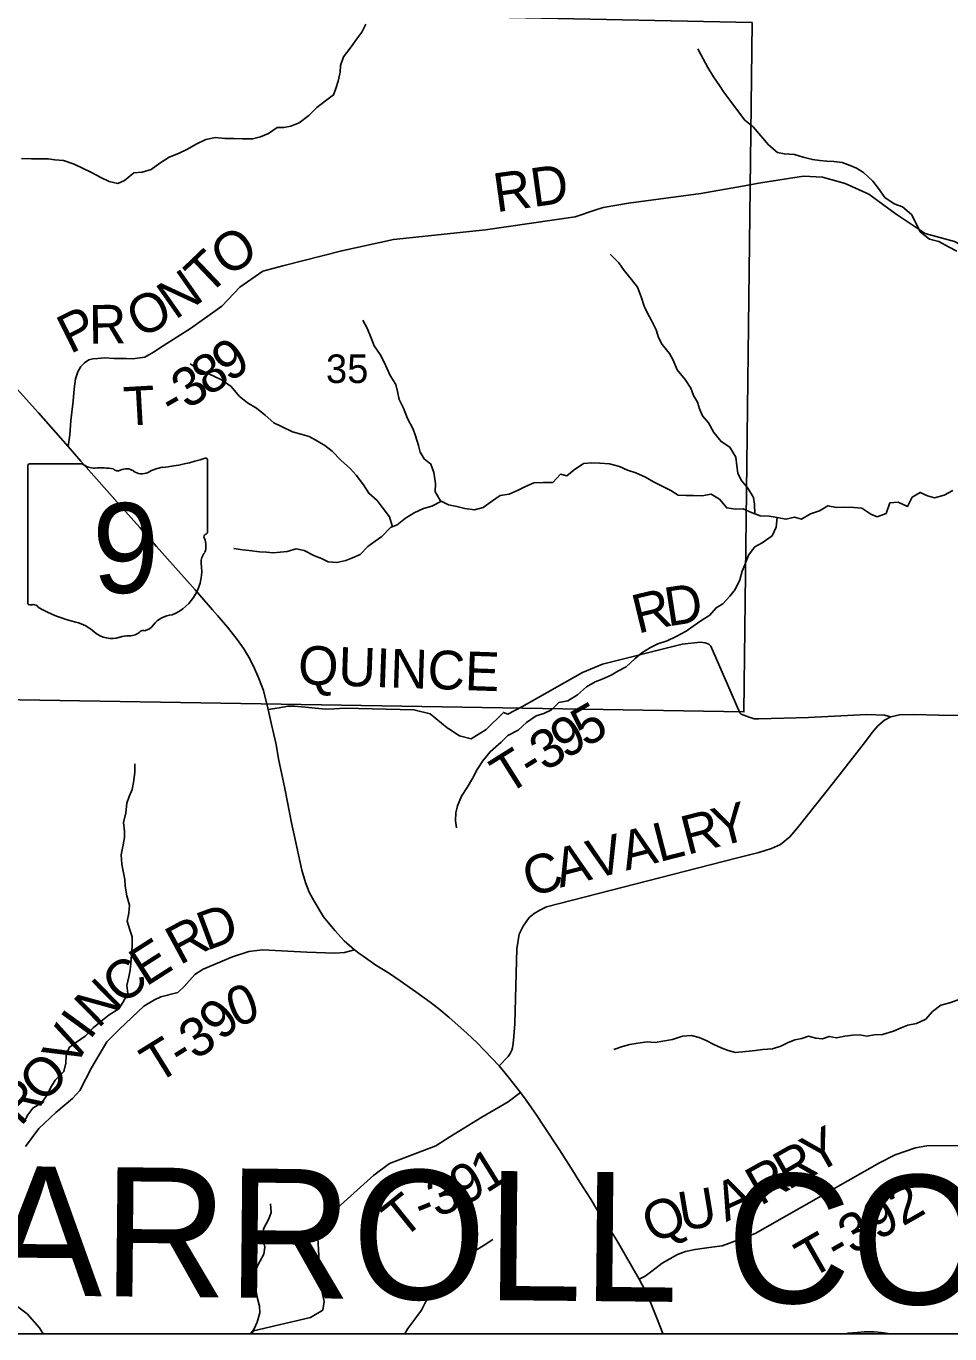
# Model space of a CAD drawing. Extents: x -3.6 to 34, y 0 to 32.8.
# Drawn here: x 0.333 to 1.688, y 26.043 to 27.961 of the extents above; entities that cross this region are included whole.
import ezdxf

# ---------------------------------------------------------------- set-up
doc = ezdxf.new("R2010")
doc.units = 0
for name, color, linetype in [('GM_X_Corporation', 7, 'Continuous'), ('GM_X_County_Road', 7, 'Continuous'), ('GM_X_County_Road_Text', 7, 'Continuous'), ('GM_X_County_Text', 7, 'Continuous'), ('GM_X_Minor_River', 7, 'Continuous'), ('GM_X_Section_Text', 7, 'Continuous'), ('GM_X_State_Location', 7, 'Continuous'), ('GM_X_State_Route', 7, 'Continuous'), ('GM_X_State_Shield', 7, 'Continuous'), ('GM_X_Township_Road', 7, 'Continuous'), ('GM_X_Township_Road_Text', 7, 'Continuous'), ('SH_Data', 7, 'Continuous')]:
    doc.layers.add(name, color=color, linetype=linetype)

msp = doc.modelspace()

# ---------------------------------------------------------------- linework, layer by layer
at = {"layer": 'GM_X_Corporation'}
for points in [[(3.1705, 28.9337), (3.1705, 32.8429), (-3.6295, 32.8429), (-3.6295, 26.0429), (2.3706, 26.0429), (2.3712, 26.0804), (2.3716, 26.1248), (2.3732, 26.2253), (2.3789, 26.6097), (2.3911, 27.5117), (2.3952, 27.9336), (2.3997, 28.282), (2.4082, 28.9473), (2.5416, 28.945), (2.5837, 28.9442), (2.8343, 28.9397)], [(1.398, 27.966), (1.386, 26.9549), (0.2053, 26.9746), (0.2336, 27.9902)]]:
    msp.add_lwpolyline(points, close=True, dxfattribs=at)
msp.add_lwpolyline([(-2.8635, 26.0429), (2.3706, 26.0429), (2.3712, 26.0804), (2.3716, 26.1248), (2.3732, 26.2253), (2.3789, 26.6097), (2.3911, 27.5117), (2.3952, 27.9336), (2.3997, 28.282), (2.4082, 28.9473), (2.5416, 28.945), (2.5837, 28.9442), (2.8343, 28.9397), (3.1705, 28.9337), (3.1705, 30.458), (3.0419, 30.4594), (1.7819, 30.4857), (1.2437, 30.4948), (0.4055, 30.5105), (0.3556, 30.5115), (0.2578, 30.5133), (0.2583, 30.5905), (-0.398, 30.5946), (-0.453, 30.5952)], dxfattribs=at)
at = {"layer": 'GM_X_County_Road'}
msp.add_lwpolyline([(1.7122, 26.9497), (1.6716, 26.9501), (1.635, 26.9512), (1.6143, 26.9507), (1.6014, 26.9478), (1.5921, 26.943), (1.5821, 26.9344), (1.5738, 26.925), (1.5643, 26.9118), (1.5175, 26.8517), (1.4643, 26.7848), (1.4532, 26.7717), (1.4394, 26.7606), (1.4261, 26.7546), (1.4077, 26.7486), (1.3746, 26.7403), (1.0964, 26.6689), (1.0864, 26.6642), (1.0783, 26.6593), (1.0708, 26.6533), (1.0621, 26.641), (1.0565, 26.629), (1.0527, 26.6073), (1.0513, 26.5535), (1.0498, 26.4974), (1.0481, 26.473), (1.0472, 26.4659), (1.0465, 26.4622), (1.0453, 26.4589), (1.0431, 26.454), (1.0402, 26.4498), (1.0268, 26.4357)], dxfattribs=at)
at = {"layer": 'GM_X_Minor_River'}
for points in [[(0.8314, 27.9639), (0.8255, 27.952), (0.8181, 27.9421), (0.81, 27.9306), (0.7985, 27.916), (0.7941, 27.903), (0.7939, 27.8931), (0.7907, 27.8802), (0.7874, 27.8695), (0.7842, 27.86), (0.7722, 27.8514), (0.7595, 27.8417), (0.7479, 27.8298), (0.7337, 27.819), (0.7213, 27.8142), (0.7111, 27.8122), (0.7013, 27.812), (0.6885, 27.8031), (0.6769, 27.7984), (0.6652, 27.7955), (0.6504, 27.7953), (0.6379, 27.7959), (0.6247, 27.7961), (0.6111, 27.7974), (0.5967, 27.7945), (0.5828, 27.7878), (0.5697, 27.7804), (0.5565, 27.7738), (0.543, 27.7686), (0.5291, 27.7597), (0.5168, 27.7504), (0.5036, 27.7468), (0.4911, 27.7455), (0.4777, 27.7343), (0.4679, 27.7299), (0.455, 27.7328), (0.4428, 27.7387), (0.4279, 27.7468), (0.4169, 27.7519), (0.4035, 27.7586), (0.3879, 27.7636), (0.3754, 27.7646), (0.3656, 27.766), (0.3512, 27.7661), (0.341, 27.7663), (0.3266, 27.7665)], [(1.698, 27.6308), (1.6858, 27.6371), (1.6716, 27.6448), (1.658, 27.6484), (1.6446, 27.6592), (1.6387, 27.6713), (1.6317, 27.6845), (1.6187, 27.6956), (1.6061, 27.7), (1.5927, 27.7093), (1.5835, 27.7228), (1.575, 27.7333), (1.5612, 27.746), (1.5512, 27.7527), (1.5417, 27.7564), (1.5299, 27.7607), (1.5178, 27.7625), (1.5076, 27.7627), (1.4973, 27.7637), (1.4863, 27.765), (1.473, 27.7686), (1.4601, 27.7726), (1.4453, 27.7735), (1.4351, 27.7753), (1.4217, 27.7868), (1.3994, 27.8131), (1.3871, 27.8231), (1.3736, 27.8408), (1.3666, 27.8505), (1.3566, 27.864), (1.35, 27.8738), (1.3411, 27.8866), (1.333, 27.9001), (1.3263, 27.9129), (1.3182, 27.9276)], [(1.4017, 27.2456), (1.4015, 27.2596), (1.3999, 27.2695), (1.3917, 27.283), (1.3817, 27.295), (1.377, 27.3052), (1.3757, 27.3158), (1.374, 27.3287), (1.3651, 27.3434), (1.3525, 27.3515), (1.3417, 27.3646), (1.3339, 27.379), (1.3251, 27.3891), (1.3208, 27.3993), (1.3176, 27.4091), (1.3121, 27.4193), (1.3078, 27.4298), (1.2997, 27.4426), (1.2881, 27.4565), (1.2819, 27.4708), (1.2768, 27.4806), (1.266, 27.4937), (1.2605, 27.5043), (1.2574, 27.5152), (1.2503, 27.5292), (1.2445, 27.5397), (1.2394, 27.5499), (1.2354, 27.5639), (1.2296, 27.5778), (1.2211, 27.5891), (1.2103, 27.6022), (1.2025, 27.6139), (1.1895, 27.6266)], [(0.8756, 27.4351), (0.8671, 27.4482), (0.8628, 27.458), (0.8585, 27.4682), (0.8523, 27.4791), (0.8438, 27.4919), (0.8387, 27.5044), (0.8332, 27.518), (0.8269, 27.5296)], [(0.8704, 27.2266), (0.866, 27.2413), (0.8556, 27.2552), (0.8479, 27.2649), (0.8356, 27.2758), (0.8282, 27.2882), (0.8174, 27.3021), (0.8082, 27.3118), (0.7948, 27.3241), (0.7821, 27.3372), (0.7714, 27.3458), (0.758, 27.3536), (0.7481, 27.3591), (0.7379, 27.362), (0.7238, 27.3656), (0.7078, 27.3737), (0.6967, 27.3792), (0.6837, 27.39), (0.6711, 27.4005), (0.6581, 27.4083), (0.6458, 27.4183), (0.6339, 27.4322), (0.6209, 27.4415), (0.6083, 27.4474), (0.5988, 27.4518), (0.5862, 27.4577), (0.5736, 27.4654)], [(1.6922, 27.2796), (1.6794, 27.2729), (1.6655, 27.2689), (1.6552, 27.2718), (1.6446, 27.2769), (1.6326, 27.2699), (1.6259, 27.2565), (1.6122, 27.2624), (1.5998, 27.2615), (1.5943, 27.2462), (1.5815, 27.2411), (1.572, 27.2451), (1.559, 27.2536), (1.5473, 27.255), (1.5336, 27.2552), (1.5215, 27.255), (1.509, 27.2574), (1.4966, 27.2497), (1.4835, 27.2457), (1.4703, 27.2379), (1.4601, 27.2408), (1.4476, 27.2375), (1.4347, 27.24), (1.423, 27.2421), (1.4097, 27.2427), (1.3979, 27.247), (1.385, 27.2529), (1.3736, 27.2524), (1.3607, 27.2541), (1.3503, 27.2668), (1.3377, 27.2746), (1.3241, 27.2721), (1.312, 27.2723), (1.3014, 27.2725), (1.2897, 27.2731), (1.2786, 27.2798), (1.2649, 27.2864), (1.2535, 27.2927), (1.2416, 27.2994), (1.2275, 27.3056), (1.2154, 27.3096), (1.2032, 27.3151), (1.1888, 27.3191), (1.1744, 27.32), (1.163, 27.3202), (1.1505, 27.3193), (1.137, 27.3103), (1.1262, 27.3014), (1.1167, 27.3036), (1.1055, 27.2916), (1.0915, 27.2914), (1.0779, 27.2912), (1.0648, 27.2849), (1.055, 27.2802), (1.0418, 27.2743), (1.0286, 27.2726), (1.0159, 27.2637), (1.0035, 27.2548), (0.9907, 27.2515), (0.9767, 27.2532), (0.9649, 27.2561), (0.9528, 27.2586), (0.941, 27.2648), (0.9332, 27.278), (0.9334, 27.2902), (0.9313, 27.3061), (0.9269, 27.3185), (0.917, 27.326), (0.9112, 27.3358), (0.9084, 27.3456), (0.9044, 27.36), (0.9008, 27.3698), (0.8926, 27.3852), (0.8867, 27.4003), (0.8805, 27.4131), (0.8777, 27.4249), (0.8756, 27.4351)], [(0.9424, 27.2641), (0.9282, 27.257), (0.9158, 27.2534), (0.9022, 27.2472), (0.8895, 27.2394), (0.8772, 27.2293), (0.8674, 27.2254), (0.8551, 27.2123), (0.8453, 27.2053), (0.8345, 27.1975), (0.8233, 27.186), (0.812, 27.1812), (0.8019, 27.1773), (0.789, 27.1741), (0.7762, 27.175), (0.7663, 27.1798), (0.756, 27.1838), (0.7411, 27.1916), (0.729, 27.1944), (0.7162, 27.1904), (0.7056, 27.1891), (0.6954, 27.1882), (0.6855, 27.1892), (0.6753, 27.1898), (0.6601, 27.1919), (0.6507, 27.1929), (0.6378, 27.1949)], [(1.4348, 27.24), (1.433, 27.2259), (1.4272, 27.2133), (1.4126, 27.2032), (1.4021, 27.197), (1.3928, 27.1851), (1.3873, 27.1709), (1.3833, 27.1614), (1.3801, 27.1488), (1.3731, 27.1347), (1.3653, 27.125), (1.3552, 27.1135), (1.3451, 27.1077), (1.3358, 27.0969), (1.3242, 27.0895), (1.3114, 27.0809), (1.3013, 27.0736), (1.2867, 27.0658), (1.2735, 27.0591), (1.2596, 27.0551), (1.2487, 27.0496), (1.236, 27.0418), (1.2263, 27.0333), (1.2132, 27.021), (1.2012, 27.0147), (1.1914, 27.0089), (1.1779, 27.003), (1.1677, 26.999), (1.155, 26.9916), (1.1419, 26.98), (1.1276, 26.9715), (1.1144, 26.9686), (1.1036, 26.9582), (1.0923, 26.9527), (1.0814, 26.9495), (1.0672, 26.9394), (1.0549, 26.9282), (1.0395, 26.9204), (1.0298, 26.9104), (1.0137, 26.8965), (1.0029, 26.8834), (0.9948, 26.8707), (0.9878, 26.8573), (0.98, 26.8443), (0.9715, 26.8316), (0.9657, 26.8171), (0.9632, 26.8068), (0.963, 26.7954), (0.9643, 26.7848)], [(0.3292, 26.3521), (0.3358, 26.3639), (0.3429, 26.3739), (0.3564, 26.3821), (0.3645, 26.394), (0.3689, 26.4039), (0.3756, 26.4151), (0.3886, 26.4274), (0.3915, 26.44), (0.3921, 26.4506), (0.3964, 26.4628), (0.4069, 26.4706), (0.42, 26.4795), (0.4316, 26.4915), (0.4454, 26.5031), (0.4551, 26.5105), (0.469, 26.5194), (0.4749, 26.529), (0.4823, 26.542), (0.481, 26.5538), (0.4838, 26.5667), (0.4856, 26.5762), (0.487, 26.5861), (0.4879, 26.5987), (0.4885, 26.6116), (0.4887, 26.6249), (0.4851, 26.6355), (0.4815, 26.648), (0.4836, 26.6598), (0.485, 26.6716), (0.481, 26.6852), (0.4785, 26.6996), (0.478, 26.7094), (0.4755, 26.7215), (0.4735, 26.7318), (0.4725, 26.7454), (0.4753, 26.7603), (0.4775, 26.7706), (0.4777, 26.7801), (0.476, 26.7926), (0.4792, 26.8071), (0.4809, 26.8211), (0.4842, 26.8311), (0.4889, 26.8414), (0.4907, 26.8517), (0.4927, 26.8661), (0.4925, 26.879)], [(1.7002, 26.5325), (1.6878, 26.5281), (1.6746, 26.5249), (1.6626, 26.5156), (1.6529, 26.5044), (1.639, 26.4981), (1.6262, 26.4956), (1.6164, 26.4917), (1.6055, 26.487), (1.5893, 26.4818), (1.5776, 26.4812), (1.5662, 26.4795), (1.5556, 26.4813), (1.5458, 26.4808), (1.5337, 26.4794), (1.5216, 26.477), (1.511, 26.4791), (1.5012, 26.4755), (1.4914, 26.4765), (1.4807, 26.4794), (1.4709, 26.4762), (1.4607, 26.4741), (1.4498, 26.4698), (1.4401, 26.4647), (1.4276, 26.4611), (1.4133, 26.4598), (1.4027, 26.4585), (1.3887, 26.4571), (1.3736, 26.4557), (1.3626, 26.4586), (1.3523, 26.4622), (1.3416, 26.4674), (1.3306, 26.4733), (1.3203, 26.4773), (1.3089, 26.4802), (1.2957, 26.4796), (1.281, 26.4748), (1.267, 26.4723), (1.2557, 26.4703), (1.244, 26.4712), (1.2304, 26.4691), (1.2187, 26.467), (1.2077, 26.4642), (1.1949, 26.4598)], [(0.6625, 26.0429), (0.6674, 26.0501), (0.6722, 26.06), (0.6761, 26.0738), (0.6756, 26.0836), (0.6724, 26.0946), (0.6704, 26.1048), (0.6683, 26.1158), (0.6678, 26.1253), (0.6695, 26.1352), (0.6736, 26.1447), (0.682, 26.1596), (0.6834, 26.1699), (0.6798, 26.1843), (0.6811, 26.1968), (0.6892, 26.2114), (0.6925, 26.2209), (0.6916, 26.2334)], [(0.8885, 26.0429), (0.8929, 26.0509), (0.9033, 26.0643), (0.913, 26.0778), (0.9192, 26.0904), (0.9281, 26.1046), (0.9382, 26.1131), (0.9528, 26.122), (0.964, 26.134), (0.9718, 26.1455), (0.9806, 26.1578), (0.9908, 26.164), (1.005, 26.1729), (1.0178, 26.1811)], [(1.6028, 26.0429), (1.6011, 26.0431), (1.5871, 26.0448), (1.5768, 26.0458), (1.5624, 26.0459), (1.5522, 26.045), (1.5386, 26.0437), (1.5355, 26.0429)]]:
    msp.add_lwpolyline(points, dxfattribs=at)
at = {"layer": 'GM_X_State_Route'}
msp.add_lwpolyline([(1.267, 26.0429), (1.2668, 26.0435), (1.2593, 26.0635), (1.2495, 26.088), (1.2411, 26.1063), (1.2325, 26.1232), (1.2119, 26.1587), (1.1988, 26.1805), (1.1842, 26.204), (1.1714, 26.2238), (1.1602, 26.242), (1.1451, 26.2654), (1.1325, 26.2859), (1.1153, 26.3127), (1.0913, 26.3488), (1.082, 26.3631), (1.0667, 26.3854), (1.058, 26.3969), (1.04, 26.4197), (1.0268, 26.4357), (0.9945, 26.4695), (0.9794, 26.484), (0.9538, 26.5069), (0.9386, 26.5194), (0.9256, 26.5293), (0.9047, 26.5447), (0.8819, 26.5606), (0.866, 26.5712), (0.8461, 26.5838), (0.8273, 26.5966), (0.8209, 26.6013), (0.815, 26.6062), (0.7998, 26.6192), (0.7857, 26.6344), (0.7695, 26.6545), (0.7554, 26.6775), (0.7481, 26.6908), (0.743, 26.7047), (0.7374, 26.7228), (0.7262, 26.7745), (0.7227, 26.7899), (0.7128, 26.8425), (0.7032, 26.8864), (0.6997, 26.9072), (0.6933, 26.9365), (0.6882, 26.9586), (0.6811, 26.9866), (0.6745, 27.0039), (0.6666, 27.0223), (0.6598, 27.0351), (0.6523, 27.0474), (0.6428, 27.0611), (0.6286, 27.0791), (0.6141, 27.0965), (0.6065, 27.1048), (0.5812, 27.1343), (0.5244, 27.1978), (0.5002, 27.2256), (0.4747, 27.2537), (0.4134, 27.3228), (0.3947, 27.3442), (0.3515, 27.3935), (0.298, 27.453)], dxfattribs=at)
at = {"layer": 'GM_X_State_Shield'}
for p, q in [((0.3355, 27.3156), (0.3355, 27.1154)), ((0.4153, 27.319), (0.3381, 27.319)), ((0.5991, 27.2193), (0.5991, 27.324)), ((0.5991, 27.2193), (0.5991, 27.2193))]:
    msp.add_line(p, q, dxfattribs=at)
for centre, radius, start, end in [((0.3385, 27.316), 0.00305, 98.1301, 188.1301), ((0.4337, 27.3422), 0.0296, 231.6195, 271.1119), ((0.4435, 27.2066), 0.1064, 80.4867, 94.9883), ((0.4677, 27.317), 0.00855, 219.7921, 297.1024), ((0.4802, 27.2939), 0.0178, 54.4667, 119.1411), ((0.5409, 27.2579), 0.0563, 97.3462, 120.7689), ((0.5052, 27.5918), 0.2796, 275.8445, 288.9065), ((0.5962, 27.3244), 0.00294, 351.8621, 97.738), ((0.5031, 27.3256), 0.0214, 233.8562, 294.8282), ((0.5985, 27.2116), 0.00454, 107.944, 210.337), ((0.596, 27.2189), 0.00314, 289.6038, 7.7341), ((0.5696, 27.1984), 0.0273, 340.033, 23.6496), ((0.6097, 27.1755), 0.0198, 136.8065, 186.9296), ((0.5209, 27.1621), 0.0699, 292.3089, 8.9858), ((0.3385, 27.115), 0.00308, 171.9584, 258.3066), ((0.339, 27.1355), 0.0235, 267.339, 280.6039), ((0.3438, 27.1039), 0.00848, 29.7484, 93.2717), ((0.4509, 27.2837), 0.2019, 240.4129, 257.1985), ((0.3907, 27.0255), 0.0632, 47.1842, 75.836), ((0.5018, 27.096), 0.0226, 282.8732, 323.2771), ((0.5504, 27.0593), 0.0383, 94.4031, 142.5768), ((0.459, 27.1029), 0.0401, 230.7004, 286.2918), ((0.4822, 27.0337), 0.0329, 85.6951, 111.2099), ((0.4851, 27.0879), 0.0214, 268.777, 315.5493), ((0.5044, 27.0685), 0.00601, 65.7517, 132.6484)]:
    msp.add_arc(centre, radius, start, end, dxfattribs=at)
at = {"layer": 'GM_X_Township_Road'}
for points in [[(1.4048, 27.7298), (1.4136, 27.7314), (1.4735, 27.7407), (1.5009, 27.7394), (1.5346, 27.7299), (1.5692, 27.7143), (1.609, 27.6852), (1.6519, 27.6569), (1.6946, 27.6449), (1.7179, 27.6327), (1.746, 27.6205), (1.7894, 27.6086), (1.8209, 27.6012), (1.8495, 27.5978), (1.8671, 27.6001)], [(1.1793, 27.6949), (1.2165, 27.7011), (1.3227, 27.7153), (1.3921, 27.7276), (1.4048, 27.7298)], [(0.3947, 27.3442), (0.3974, 27.3615), (0.399, 27.3822), (0.4023, 27.4106), (0.4038, 27.4288), (0.4058, 27.4434), (0.4088, 27.4539), (0.4134, 27.4617), (0.4186, 27.467), (0.4252, 27.4712), (0.4311, 27.4728), (0.4384, 27.4735), (0.4482, 27.4743), (0.4622, 27.4734), (0.4802, 27.4732), (0.4896, 27.473), (0.5071, 27.4751), (0.5199, 27.4826), (0.5342, 27.4919), (0.5741, 27.5172), (0.6203, 27.5501), (0.6468, 27.5779), (0.6805, 27.6012), (0.7096, 27.6094), (0.7962, 27.6315), (0.8719, 27.6481), (1.007, 27.6621), (1.1386, 27.6811), (1.1673, 27.6908), (1.1793, 27.6949)], [(0.9679, 26.9206), (0.9687, 26.9201), (0.9859, 26.9155), (1.008, 26.9294), (1.0333, 26.9543), (1.0399, 26.9518), (1.0602, 26.9625), (1.1492, 27.0128), (1.1786, 27.0249), (1.2951, 27.0542), (1.3224, 27.0575), (1.329, 27.0564), (1.3343, 27.0542), (1.3374, 27.0513), (1.3623, 26.9941), (1.3799, 26.9537), (1.3818, 26.9517), (1.3937, 26.9473), (1.4011, 26.9451), (1.4079, 26.9449), (1.4805, 26.9469), (1.5664, 26.9514), (1.5923, 26.9503), (1.6014, 26.9478)], [(0.6882, 26.9586), (0.7044, 26.9611), (0.717, 26.9633), (0.7271, 26.9636), (0.7724, 26.959), (0.785, 26.9596)], [(0.785, 26.9596), (0.8004, 26.9605), (0.902, 26.9582), (0.9257, 26.9522), (0.9505, 26.9319), (0.9555, 26.9287), (0.9679, 26.9206)], [(0.815, 26.6062), (0.8, 26.6022), (0.7861, 26.6012), (0.7449, 26.6026), (0.6801, 26.6062), (0.6598, 26.6035), (0.636, 26.5958), (0.5927, 26.5778), (0.5807, 26.5701), (0.5649, 26.5522), (0.5556, 26.5437), (0.5307, 26.5369), (0.5217, 26.5327), (0.506, 26.5234), (0.4699, 26.4898), (0.4514, 26.4709), (0.4289, 26.433), (0.412, 26.3996), (0.4011, 26.3882), (0.3769, 26.3673), (0.352, 26.344), (0.3321, 26.3177)], [(1.058, 26.3969), (1.04, 26.3832), (1.0017, 26.3607), (0.9547, 26.3319), (0.9343, 26.3185), (0.8661, 26.2925), (0.8433, 26.2757), (0.7601, 26.2007), (0.7632, 26.149), (0.766, 26.1099), (0.7702, 26.0902), (0.7682, 26.0776), (0.7502, 26.0666), (0.6666, 26.0472), (0.6639, 26.0429)], [(1.2325, 26.1232), (1.241, 26.1275), (1.2507, 26.1349), (1.2661, 26.1463), (1.2885, 26.1593), (1.3003, 26.1635), (1.3142, 26.1666), (1.3351, 26.1697), (1.3539, 26.1718), (1.3688, 26.1775), (1.4026, 26.19), (1.5847, 26.2936), (1.6076, 26.3056), (1.6374, 26.3158), (1.6541, 26.3184), (1.861, 26.3204)], [(0.3584, 26.0429), (0.353, 26.0518), (0.3347, 26.072), (0.3173, 26.0853)]]:
    msp.add_lwpolyline(points, dxfattribs=at)
at = {"layer": 'SH_Data'}
msp.add_line((-3.6295, 26.0429), (3.1705, 26.0429), dxfattribs=at)

# ---------------------------------------------------------------- texts
at = {"layer": 'GM_X_County_Road_Text'}
for s, rotation, p in [('Y', 14.5707, (1.348, 26.7567)), ('R', 14.4329, (1.3026, 26.7451)), ('V', 14.4338, (1.1646, 26.7095)), ('A', 14.4321, (1.213, 26.722)), ('L', 14.4323, (1.2615, 26.7345)), ('A', 14.5557, (1.1162, 26.697)), ('C', 18.696, (1.0731, 26.6823))]:
    msp.add_text(s, height=0.0568, rotation=rotation, dxfattribs=at).set_placement(p)
at = {"layer": 'GM_X_County_Text'}
msp.add_text('CARROLL COUNTY', height=0.189394, rotation=359.4336, dxfattribs=at).set_placement((0.0928, 26.1015))
at = {"layer": 'GM_X_Section_Text'}
msp.add_text('35', height=0.04186, rotation=0, dxfattribs=at).set_placement((0.7729, 27.4374))
at = {"layer": 'GM_X_State_Location'}
for s in ['s', 'r']:
    msp.add_text(s, height=0.000189, dxfattribs=at).set_placement((0.4643, 27.2022))
msp.add_text('9', height=0.000189, rotation=0, dxfattribs=at).set_placement((0.4358, 27.1884))
at = {"layer": 'GM_X_State_Shield'}
msp.add_text('9', height=0.1318, dxfattribs=at).set_placement((0.4302, 27.1295))
at = {"layer": 'GM_X_Township_Road_Text'}
for s, height, rotation, p in [('RD', 0.05682, 7.9203, (1.0227, 27.6878)), ('O', 0.0568, 34.271, (0.6288, 27.5916)), ('T', 0.0568, 43.6419, (0.5999, 27.5638)), ('N', 0.0568, 34.992, (0.5517, 27.5292)), ('O', 0.0568, 26.7706, (0.4994, 27.5021)), ('P', 0.0568, 26.4737, (0.3978, 27.4794)), ('R', 0.0568, 0.6538, (0.4255, 27.495)), ('9', 0.0568, 34.83, (0.6311, 27.4372)), ('8', 0.0568, 32.8152, (0.5999, 27.417)), ('3', 0.0568, 32.2136, (0.5697, 27.398)), ('T', 0.0568, 3.2352, (0.4775, 27.3745)), ('-', 0.0568, 29.8004, (0.5472, 27.385)), ('D', 0.0568, 8.8155, (1.2742, 27.0803)), ('R', 0.0568, 13.6321, (1.2301, 27.0695)), ('QUINCE', 0.05682, 358.0023, (0.7313, 26.9956)), ('5', 0.0568, 29.7178, (1.1539, 26.9023)), ('9', 0.0568, 30.1699, (1.1237, 26.8848)), ('3', 0.0568, 30.9655, (1.0939, 26.8669)), ('T', 0.0568, 32.1221, (1.0383, 26.8322)), ('-', 0.0568, 31.6967, (1.0742, 26.8547)), ('D', 0.0568, 20.4149, (0.5976, 26.6043)), ('R', 0.0568, 28.3614, (0.5584, 26.583)), ('E', 0.0568, 32.6096, (0.5088, 26.5513)), ('C', 0.0568, 38.0182, (0.4732, 26.5234)), ('N', 0.0568, 44.4603, (0.4388, 26.4895)), ('0', 0.0568, 20.6011, (0.6403, 26.4916)), ('9', 0.0568, 44.3344, (0.6205, 26.4705)), ('I', 0.0568, 53.9342, (0.4267, 26.4725)), ('3', 0.0568, 32.6681, (0.5811, 26.4437)), ('V', 0.0568, 62.5939, (0.4048, 26.43)), ('T', 0.0568, 31.8123, (0.5245, 26.4085)), ('O', 0.0568, 43.8485, (0.3567, 26.3792)), ('-', 0.0568, 31.9671, (0.5607, 26.431)), ('R', 0.0568, 46.5374, (0.3251, 26.3459)), ('Y', 0.0568, 29.7715, (1.4912, 26.2761)), ('R', 0.0568, 29.7687, (1.4507, 26.2529)), ('1', 0.0568, 31.9048, (1.0079, 26.2484)), ('R', 0.0568, 29.5833, (1.41, 26.2298)), ('3', 0.0568, 21.8681, (0.9353, 26.2131)), ('9', 0.0568, 29.6395, (0.9753, 26.2298)), ('U', 0.0568, 9.4336, (1.2947, 26.1936)), ('A', 0.0568, 24.5446, (1.3596, 26.2066)), ('T-392', 0.05682, 29.7097, (1.483, 26.1225)), ('T', 0.0568, 38.8365, (0.8844, 26.18)), ('Q', 0.0568, 24.0163, (1.2527, 26.1743)), ('-', 0.0568, 21.9065, (0.9137, 26.2044))]:
    msp.add_text(s, height=height, rotation=rotation, dxfattribs=at).set_placement(p)

doc.saveas('drawing.dxf')
